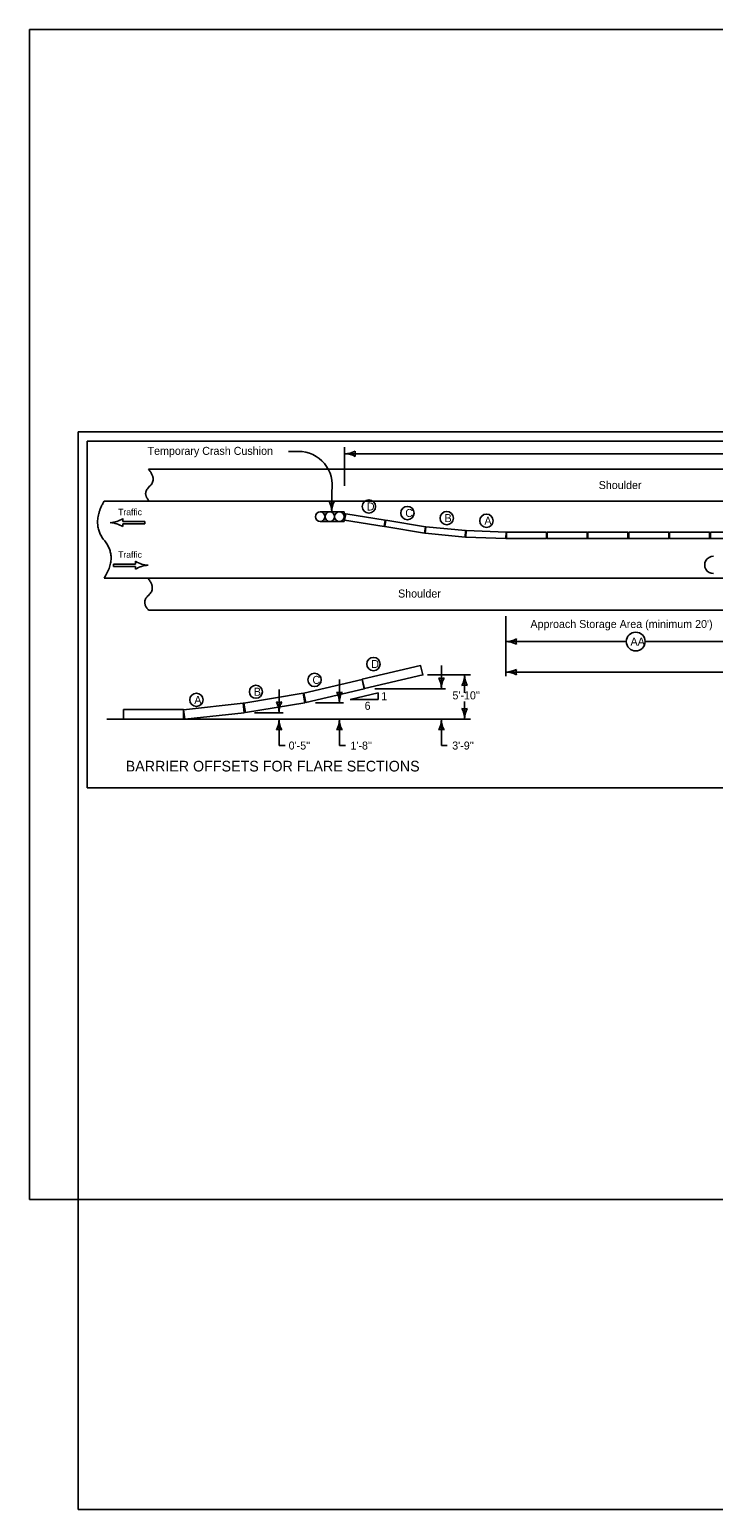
# Model space of a CAD drawing. Extents: x 10041 to 81668, y 7924 to 11018.
# Drawn here: x 10041 to 11324, y 7924 to 10698 of the extents above; entities that cross this region are included whole.
import ezdxf

# ---------------------------------------------------------------- set-up
doc = ezdxf.new("R2010")
doc.units = 0
for name, color, linetype in [('dsnCellElements', 7, 'Continuous'), ('Level 1', 7, 'Continuous'), ('Level 10', 7, 'Continuous'), ('Level 12', 7, 'Continuous'), ('Level 5', 7, 'Continuous'), ('Level 6', 7, 'Continuous'), ('SheetBorder', 7, 'Continuous')]:
    doc.layers.add(name, color=color, linetype=linetype)

msp = doc.modelspace()

# ---------------------------------------------------------------- linework, layer by layer
at = {"layer": 'dsnCellElements'}
msp.add_lwpolyline([(10041.2, 8505), (13362.1, 8505), (13362.1, 10698.4), (10041.2, 10698.4)], close=True, dxfattribs=at)
at = {"layer": 'Level 1'}
for p, q in [((10545.5, 9907.5), (10526.8, 9907.5)), ((10632, 9915.8), (10632, 9843.3)), ((10632, 9903.1), (11564.9, 9903.1)), ((10264.4, 9874.1), (11392.9, 9874.1)), ((10607.8, 9832.9), (10607.8, 9794.2)), ((10180.8, 9814.1), (11422.9, 9814.1)), ((10586.2, 9794.2), (10631.2, 9794.2)), ((10631.2, 9794.2), (10631.2, 9776.2)), ((10192.3, 9774), (10192.3, 9774)), ((10216.2, 9781.5), (10216.2, 9776.3)), ((10216.2, 9776.3), (10257.5, 9776.3)), ((10257.5, 9771.8), (10216.2, 9771.8)), ((10216.2, 9771.8), (10216.2, 9766.5)), ((10257.5, 9776.3), (10257.5, 9771.8)), ((10631.2, 9776.2), (10586.2, 9776.2)), ((10630, 9781.9), (10631.2, 9781.7)), ((10631.7, 9778.3), (10631.7, 9778.3)), ((10239.8, 9696.4), (10198.6, 9696.4)), ((10198.6, 9696.4), (10198.6, 9691.9)), ((10198.6, 9691.9), (10239.8, 9691.9)), ((10239.8, 9701.6), (10239.8, 9696.4)), ((10239.8, 9691.9), (10239.8, 9686.6)), ((10263.7, 9694.1), (10263.7, 9694.1)), ((10180.8, 9670.1), (11422.9, 9670.1)), ((10264.4, 9610.1), (11392.9, 9610.1)), ((10934.2, 9598.9), (10934.2, 9486.5)), ((10934.2, 9551.1), (11160.3, 9551.1)), ((11195.6, 9551.1), (11421.7, 9551.1)), ((10787.5, 9488.7), (10867.9, 9488.7)), ((10813.5, 9506.2), (10813.5, 9462.7)), ((10857.1, 9488.7), (10857.1, 9455.2)), ((10934.2, 9494), (11525, 9494)), ((10509.1, 9461.2), (10509.1, 9417.7)), ((10622.3, 9479.8), (10622.3, 9436.3)), ((10688.6, 9462.7), (10821.2, 9462.7)), ((10577.3, 9436.3), (10630.1, 9436.3)), ((10857.1, 9438.9), (10857.1, 9405.4)), ((10186.1, 9405.4), (10867.9, 9405.4)), ((10463.1, 9417.7), (10516.8, 9417.7)), ((10509.1, 9405.4), (10509.1, 9378.5)), ((10622.3, 9405.4), (10622.3, 9356.1)), ((10813.5, 9405.4), (10813.5, 9356.1)), ((10509.1, 9378.5), (10509.1, 9356.1)), ((10509.1, 9356.1), (10520.2, 9356.1)), ((10622.3, 9356.1), (10633.5, 9356.1)), ((10813.5, 9356.1), (10824.6, 9356.1))]:
    msp.add_line(p, q, dxfattribs=at)
for points in [[(10708, 9778.7), (10634, 9790.8), (10632, 9778.9), (10706, 9766.8)], [(10783.5, 9766.3), (10709.5, 9778.4), (10707.5, 9766.6), (10781.5, 9754.4)], [(10858.9, 9759.1), (10784.2, 9766.2), (10783.1, 9754.2), (10857.8, 9747.1)], [(10934.7, 9756.1), (10859.7, 9759.1), (10859.3, 9747.1), (10934.2, 9744.1)], [(10935.4, 9756.1), (11010.4, 9756.1), (11010.4, 9744.1), (10935.4, 9744.1)], [(11011.9, 9756.1), (11086.9, 9756.1), (11086.9, 9744.1), (11011.9, 9744.1)], [(11088.4, 9756.1), (11163.4, 9756.1), (11163.4, 9744.1), (11088.4, 9744.1)], [(11164.9, 9756.1), (11239.9, 9756.1), (11239.9, 9744.1), (11164.9, 9744.1)], [(11241.4, 9756.1), (11316.4, 9756.1), (11316.4, 9744.1), (11241.4, 9744.1)], [(11317.9, 9756.1), (11392.9, 9756.1), (11392.9, 9744.1), (11317.9, 9744.1)], [(10665.1, 9480.3), (10774.6, 9506.2), (10778.7, 9488.7), (10669.3, 9462.8)], [(10555.3, 9454.3), (10664.8, 9480.2), (10668.9, 9462.7), (10559.4, 9436.8)], [(10330.1, 9423.3), (10441.9, 9435.6), (10443.9, 9417.7), (10332.1, 9405.4)], [(10443.2, 9435.6), (10554.2, 9454.1), (10557.1, 9436.3), (10446.2, 9417.9)], [(10217.6, 9423.5), (10330.1, 9423.4), (10330.1, 9405.4), (10217.6, 9405.5)]]:
    msp.add_lwpolyline(points, close=True, dxfattribs=at)
for centre, radius in [((10586.2, 9785.2), 9), ((10586.2, 9785.2), 9), ((10604.2, 9785.2), 9), ((10604.2, 9785.2), 9), ((10622.2, 9785.2), 9), ((10622.2, 9785.2), 9), ((10677.5, 9804.3), 12.5), ((10749.7, 9792.1), 12.5), ((10823.5, 9782.5), 12.5), ((10898, 9777.6), 12.5), ((11177.9, 9551.1), 17.6), ((10686, 9509), 12.5), ((10575.6, 9479.2), 12.5), ((10465.6, 9457), 12.2), ((10354, 9441.8), 12.5)]:
    msp.add_circle(centre, radius, dxfattribs=at)
for centre, radius, start, end in [((10545.5, 9844.2), 63.3, 349.6463, 90), ((10632, 9945.6), 42.5, 270, 298.0725), ((10667.7, 9903.1), 16.4, 162.2666, 197.7334), ((10632, 9860.6), 42.5, 61.9275, 90), ((10607.8, 9829.9), 16.4, 252.2666, 287.7333), ((10565.3, 9794.2), 42.5, 360, 28.0725), ((10650.3, 9794.2), 42.5, 151.9275, 180), ((10190.3, 9822.3), 48.4, 272.352, 302.382), ((10190.3, 9725.7), 48.4, 57.618, 87.648), ((10265.7, 9742.5), 48.4, 237.618, 267.648), ((10265.7, 9645.8), 48.4, 92.352, 122.382), ((10934.2, 9593.6), 42.5, 270, 298.0725), ((10934.2, 9508.6), 42.5, 61.9275, 90), ((10969.8, 9551.1), 16.4, 162.2666, 197.7334), ((10814.6, 9488.7), 42.5, 331.9275, 360), ((10899.6, 9488.7), 42.5, 180, 208.0725), ((10934.2, 9536.5), 42.5, 270, 298.0725), ((10934.2, 9451.5), 42.5, 61.9275, 90), ((10969.8, 9494), 16.4, 162.2666, 197.7334), ((10813.5, 9498.4), 16.4, 252.2666, 287.7333), ((10771, 9462.7), 42.5, 360, 28.0725), ((10856, 9462.7), 42.5, 151.9275, 180), ((10857.1, 9453.1), 16.4, 72.2666, 107.7334), ((10509.1, 9453.4), 16.4, 252.2666, 287.7333), ((10466.6, 9417.7), 42.5, 360, 28.0725), ((10551.6, 9417.7), 42.5, 151.9275, 180), ((10622.3, 9471.9), 16.4, 252.2666, 287.7333), ((10579.8, 9436.3), 42.5, 360, 28.0725), ((10664.8, 9436.3), 42.5, 151.9275, 180), ((10466.6, 9405.4), 42.5, 331.9275, 360), ((10551.6, 9405.4), 42.5, 180, 208.0725), ((10579.8, 9405.4), 42.5, 331.9275, 360), ((10664.8, 9405.4), 42.5, 180, 208.0725), ((10771, 9405.4), 42.5, 331.9275, 360), ((10856, 9405.4), 42.5, 180, 208.0725), ((10857.1, 9441.1), 16.4, 252.2666, 287.7333), ((10814.6, 9405.4), 42.5, 360, 28.0725), ((10899.6, 9405.4), 42.5, 151.9275, 180), ((10509.1, 9369.8), 16.4, 72.2666, 107.7334), ((10622.3, 9369.8), 16.4, 72.2666, 107.7334), ((10813.5, 9369.8), 16.4, 72.2666, 107.7334)]:
    msp.add_arc(centre, radius, start, end, dxfattribs=at)
for points in [[(10264.4, 9874.1), (10280.5, 9854.8), (10251.6, 9829.2), (10266, 9814.2)], [(10180.8, 9814.1), (10156.2, 9771.5), (10206.9, 9709.3), (10180.8, 9670.1)], [(10262.8, 9670.1), (10278.9, 9650.8), (10249.9, 9625.2), (10264.4, 9610.1)]]:
    msp.add_open_spline(points, degree=2, dxfattribs=at)
at = {"layer": 'Level 10'}
for p, q in [((10149.1, 9926.7), (13254.1, 9926.7)), ((10149.1, 9276.7), (10149.1, 9926.7))]:
    msp.add_line(p, q, dxfattribs=at)
msp.add_ellipse((11323.6, 9694.8), major_axis=(-16.3, 0), ratio=0.995025, start_param=4.712389, end_param=7.853982, dxfattribs=at)
at = {"layer": 'Level 12'}
for p, q in [((10642.4, 9442.3), (10695, 9454.8)), ((10695, 9442.3), (10642.4, 9442.3)), ((10695, 9454.8), (10695, 9442.3))]:
    msp.add_line(p, q, dxfattribs=at)
at = {"layer": 'Level 5'}
msp.add_line((13254.1, 9276.7), (10149.1, 9276.7), dxfattribs=at)
at = {"layer": 'SheetBorder'}
msp.add_lwpolyline([(10132.5, 9944), (13267.5, 9944), (13267.5, 7924), (10132.5, 7924)], close=True, dxfattribs=at)

# ---------------------------------------------------------------- texts
at = {"layer": 'Level 12'}
for s, height, p in [('Temporary Crash Cushion', 15, (10262.4, 9901.1)), ('Shoulder', 15, (11108.5, 9837)), ('Traffic', 12, (10207.3, 9788)), ('D', 15, (10673.6, 9796.8)), ('C', 15, (10745.8, 9784.6)), ('B', 15, (10819.5, 9775)), ('A', 15, (10894.1, 9770.1)), ('Traffic', 12, (10207.3, 9708.1)), ('Shoulder', 15, (10732.2, 9633.6)), ("Approach Storage Area (minimum 20')", 15, (10980.5, 9576.5)), ('AA', 15, (11168.2, 9543.6)), ('D', 15, (10682, 9501.5)), ('B', 15, (10461.7, 9449.5)), ('C', 15, (10571.7, 9471.7)), ('A', 15, (10350.1, 9434.3)), ('6', 15, (10669.5, 9423.1)), ('1', 15, (10700.7, 9441.2)), ("5'-10''", 15, (10834.2, 9442.7)), ("0'-5''", 15, (10527, 9348.6)), ("1'-8''", 15, (10642.9, 9348.6)), ("3'-9''", 15, (10833.8, 9348.6))]:
    msp.add_text(s, height=height, dxfattribs=at).set_placement(p)
at = {"layer": 'Level 6'}
msp.add_text('BARRIER OFFSETS FOR FLARE SECTIONS', height=20, dxfattribs=at).set_placement((10221.4, 9307.5))

doc.saveas('drawing.dxf')
